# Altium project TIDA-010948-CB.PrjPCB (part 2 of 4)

## Sheet TIDA-010948-CB-Debug.SchDoc
size 431 x 279 mm; Date: Not shown in title block; ApprovedBy: Not shown in title block; CheckedBy: Not shown in title block; Author: Not shown in title block; CompanyName: Not shown in title block; Engineer: Not shown in title block; Organization: Not shown in title block; Address1: Not shown in title block; Address2: Not shown in title block; Address3: Not shown in title block; Address4: Not shown in title block; DocumentNumber: 4; Revision: Use project parameter SCH_Rev; SheetNumber: 4; SheetTotal: 11; PageSetup: Record=PageOptions¦CenterHorizontal=True¦CenterVertical=True¦PrintScale=1.00¦XCorrection=1.00¦YCorrection=1.00¦PrintKind=0¦BorderSize=5000000¦LeftOffset=0¦BottomOffset=0¦Orientation=2¦PaperLength=1000¦PaperWidth=1000¦Scale=100¦PaperSource=15¦PrintQuality=600¦MediaType=1¦DitherType=10¦PaperKind=Letter¦PrintScaleMode=1
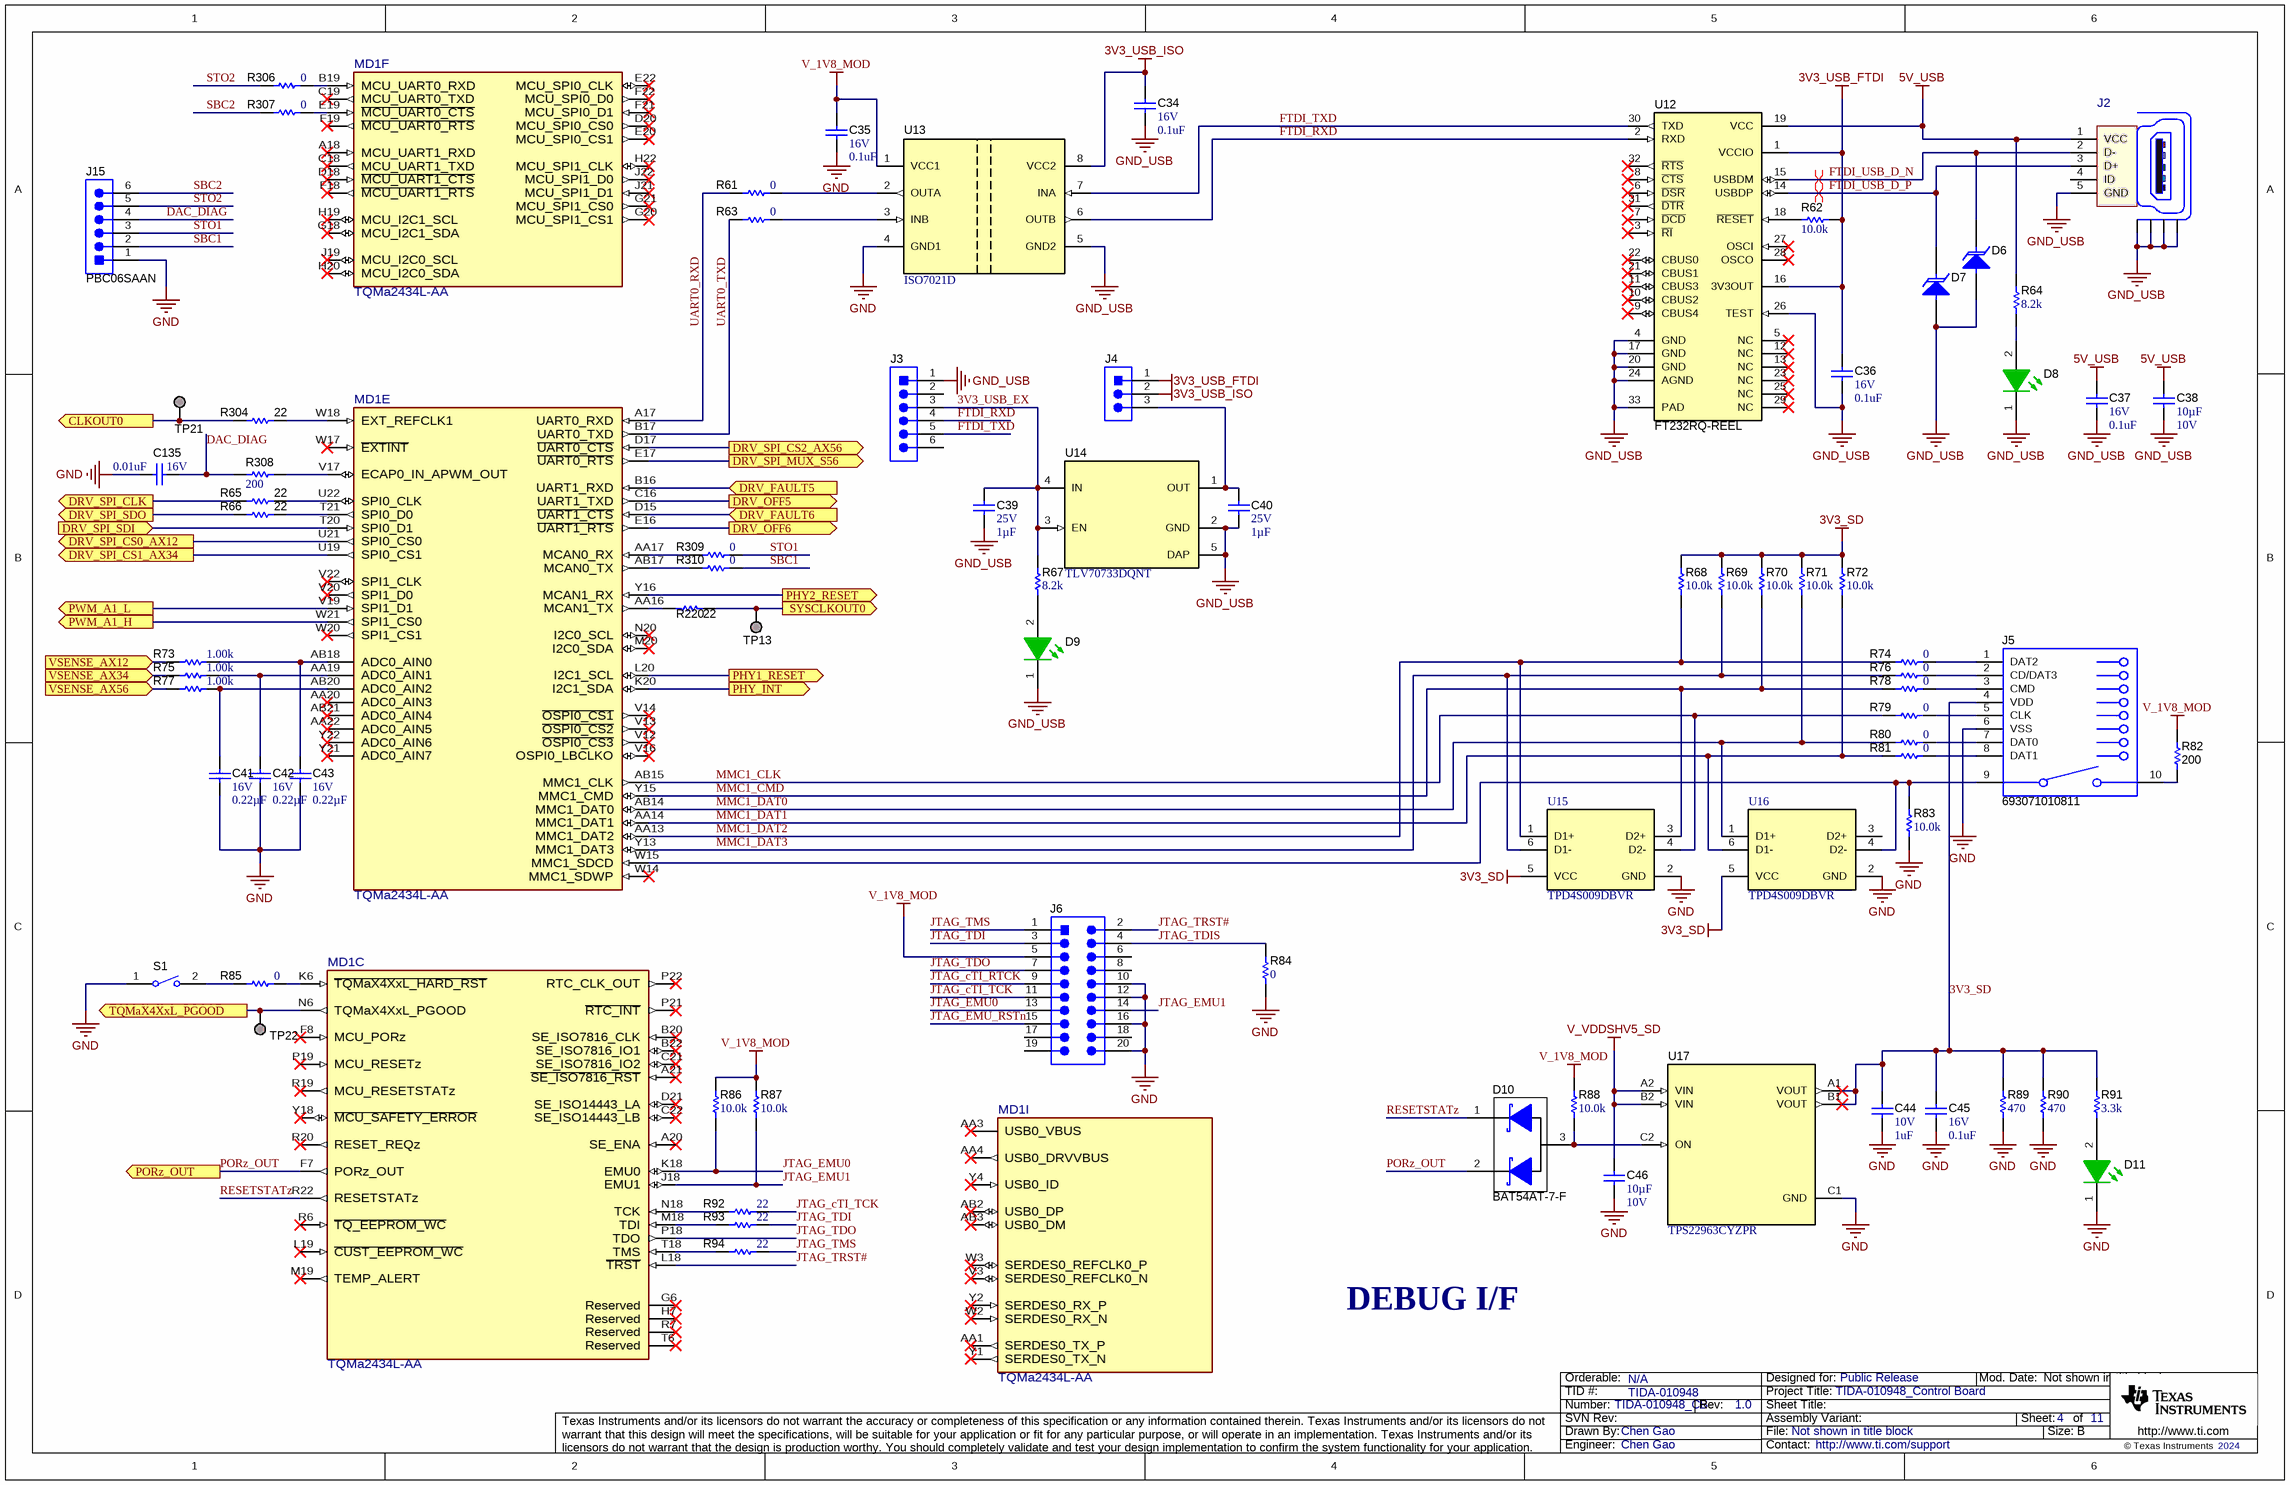
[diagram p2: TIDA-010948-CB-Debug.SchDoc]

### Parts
C34  VDC_V: 16V  ValueDisplayed: 0.1uF  [0402L]  (hidden comment: 885012105016)
C35  VDC_V: 16V  ValueDisplayed: 0.1uF  [0402L]  (hidden comment: 885012105016)
C36  VDC_V: 16V  ValueDisplayed: 0.1uF  [0402L]  (hidden comment: 885012105016)
C37  VDC_V: 16V  ValueDisplayed: 0.1uF  [0402L]  (hidden comment: 885012105016)
C38  Cap_F: 10µF  VDC_V: 10V  [0805L]  (hidden comment: 885012207026)
C39  VDC_V: 25V  ValueDisplayed: 1µF  [0402L]  (hidden comment: GRM155R61E105MA12D)
C40  VDC_V: 25V  ValueDisplayed: 1µF  [0402L]  (hidden comment: GRM155R61E105MA12D)
C41  VDC_V: 16V  ValueDisplayed: 0.22µF  [0402]  (hidden comment: GCM155R71C224KE02D)
C42  VDC_V: 16V  ValueDisplayed: 0.22µF  [0402]  (hidden comment: GCM155R71C224KE02D)
C43  VDC_V: 16V  ValueDisplayed: 0.22µF  [0402]  (hidden comment: GCM155R71C224KE02D)
C44  VDC_V: 10V  ValueDisplayed: 1uF  [0402L]  (hidden comment: 885012105012)
C45  VDC_V: 16V  ValueDisplayed: 0.1uF  [0402L]  (hidden comment: 885012105016)
C46  Cap_F: 10µF  VDC_V: 10V  [0805_HV]  (hidden comment: 885012207026)
C135  VDC_V: 16V  ValueDisplayed: 0.01uF  [0402]  (hidden comment: C1005X7R1C103K050BA)
D6  ESD321DPYR  [DPY0002A]  (value not drawn)
D7  ESD321DPYR  [DPY0002A]  (value not drawn)
D8  150040GS73240  [WL-SMCC_0402_Green]  (value not drawn)
D9  150040GS73240  [WL-SMCC_0402_Green]  (value not drawn)
D10  BAT54AT-7-F  [SOT-523]
D11  150040GS73240  [WL-SMCC_0402_Green]  (value not drawn)
J2  629105150521  [FP-629105150521_CONN_USB_8MM0_6MM6-MFG]  (value not drawn)
J3  61300611121  [WURTH_61300611121]  (value not drawn)
J4  61300311121  [WURTH_61300311121]  (value not drawn)
J5  693071010811  [Molex_693071010811]
J6  FTR-110-51-S-D-06  [Samtec_FTR-110-51-x-D-06]  (value not drawn)
J15  PBC06SAAN  [Sullins_PxC06SAAN]
MD1  TQMa2434L-AA  [FP-TQMa2434L-AA_LGA366-MFG]  (parts C,E,F,I of 9)
R61  ValueDisplayed: 0  [0402L]  (hidden comment: ERJ-2GE0R00X)
R62  ValueDisplayed: 10.0k  [0402L]  (hidden comment: CRCW040210K0FKED)
R63  ValueDisplayed: 0  [0402L]  (hidden comment: ERJ-2GE0R00X)
R64  ValueDisplayed: 8.2k  [0402L]  (hidden comment: CRCW04028K20JNED)
R65  ValueDisplayed: 22  [0402]  (hidden comment: CRCW040222R0JNED)
R66  ValueDisplayed: 22  [0402]  (hidden comment: CRCW040222R0JNED)
R67  ValueDisplayed: 8.2k  [0402L]  (hidden comment: CRCW04028K20JNED)
R68  ValueDisplayed: 10.0k  [0402L]  (hidden comment: CRCW040210K0FKED)
R69  ValueDisplayed: 10.0k  [0402L]  (hidden comment: CRCW040210K0FKED)
R70  ValueDisplayed: 10.0k  [0402L]  (hidden comment: CRCW040210K0FKED)
R71  ValueDisplayed: 10.0k  [0402L]  (hidden comment: CRCW040210K0FKED)
R72  ValueDisplayed: 10.0k  [0402L]  (hidden comment: CRCW040210K0FKED)
R73  ValueDisplayed: 1.00k  [0402L]  (hidden comment: CRCW04021K00FKED)
R74  ValueDisplayed: 0  [0402L]  (hidden comment: ERJ-2GE0R00X)
R75  ValueDisplayed: 1.00k  [0402L]  (hidden comment: CRCW04021K00FKED)
R76  ValueDisplayed: 0  [0402L]  (hidden comment: ERJ-2GE0R00X)
R77  ValueDisplayed: 1.00k  [0402L]  (hidden comment: CRCW04021K00FKED)
R78  ValueDisplayed: 0  [0402L]  (hidden comment: ERJ-2GE0R00X)
R79  ValueDisplayed: 0  [0402L]  (hidden comment: ERJ-2GE0R00X)
R80  ValueDisplayed: 0  [0402L]  (hidden comment: ERJ-2GE0R00X)
R81  ValueDisplayed: 0  [0402L]  (hidden comment: ERJ-2GE0R00X)
R82  ValueDisplayed: 200  [0402L]  (hidden comment: CRCW0402200RFKED)
R83  ValueDisplayed: 10.0k  [0402L]  (hidden comment: CRCW040210K0FKED)
R84  ValueDisplayed: 0  [0402L]  (hidden comment: ERJ-2GE0R00X)
R85  ValueDisplayed: 0  [0402L]  (hidden comment: ERJ-2GE0R00X)
R86  ValueDisplayed: 10.0k  [0402L]  (hidden comment: CRCW040210K0FKED)
R87  ValueDisplayed: 10.0k  [0402L]  (hidden comment: CRCW040210K0FKED)
R88  ValueDisplayed: 10.0k  [0402L]  (hidden comment: CRCW040210K0FKED)
R89  ValueDisplayed: 470  [0402L]  (hidden comment: CRCW0402470RJNED)
R90  ValueDisplayed: 470  [0402L]  (hidden comment: CRCW0402470RJNED)
R91  ValueDisplayed: 3.3k  [0402L]  (hidden comment: CRCW04023K30JNED)
R92  ValueDisplayed: 22  [0402L]  (hidden comment: CRCW040222R0JNED)
R93  ValueDisplayed: 22  [0402L]  (hidden comment: CRCW040222R0JNED)
R94  ValueDisplayed: 22  [0402L]  (hidden comment: CRCW040222R0JNED)
R220  ValueDisplayed: 22  [0402]  (hidden comment: CRCW040222R0JNED)
R304  ValueDisplayed: 22  [0402]  (hidden comment: CRCW040222R0JNED)
R306  ValueDisplayed: 0  [0402L]  (hidden comment: ERJ-2GE0R00X)
R307  ValueDisplayed: 0  [0402L]  (hidden comment: ERJ-2GE0R00X)
R308  ValueDisplayed: 200  [0402]  (hidden comment: CRCW0402200RFKED)
R309  ValueDisplayed: 0  [0402L]  (hidden comment: ERJ-2GE0R00X)
R310  ValueDisplayed: 0  [0402L]  (hidden comment: ERJ-2GE0R00X)
S1  434121025816  [SW_434121025816]  (value not drawn)
TP13  TESTPOINT  [TP_25MIL-SMT]  (value not drawn)  (no BOM)
TP21  TESTPOINT  [TP_25MIL-SMT]  (value not drawn)  (no BOM)
TP22  TESTPOINT  [TP_25MIL-SMT]  (value not drawn)  (no BOM)
U12  FT232RQ-REEL  [QFN32-5x5MM]
U13  PartNumber: ISO7021D  [D0008B_HV]  (hidden comment: ISO7721D)
U14  TLV70733DQNT  [DQN0004A]
U15  TPD4S009DBVR  [DBV0006A_L]
U16  TPD4S009DBVR  [DBV0006A_L]
U17  TPS22963CYZPR  [YZP0006AFAF]

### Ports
CLKOUT0 (out), DRV_FAULT5 (in), DRV_FAULT6 (in), DRV_OFF5 (out), DRV_OFF6 (out), DRV_SPI_CLK (out), DRV_SPI_CS0_AX12 (out), DRV_SPI_CS1_AX34 (out), DRV_SPI_CS2_AX56 (out), DRV_SPI_MUX_S56 (out), DRV_SPI_SDI (in), DRV_SPI_SDO (out), PHY1_RESET (out), PHY2_RESET (out), PHY_INT (out), PORz_OUT (out), PWM_A1_H (out), PWM_A1_L (out), SYSCLKOUT0 (out), TQMaX4XxL_PGOOD (out), VSENSE_AX12 (in), VSENSE_AX34 (in), VSENSE_AX56 (in)

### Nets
3V3_SD: C44.1 C45.1 J5.4(VDD) R68.2 R69.2 R70.2 R71.2 R72.2 R89.2 R90.2 R91.2 U15.5(VCC) U16.5(VCC) U17.A1(VOUT) U17.B1(VOUT)
3V3_USB_FTDI: C36.1 J4.1 R62.1 U12.1(VCCIO) U12.16(3V3OUT)
3V3_USB_ISO: C34.1 J4.2 U13.8(VCC2)
5V_USB: C37.1 C38.1 J2.1(VCC) R64.2 U12.19(VCC)
GND: C35.2 C41.1 C42.1 C43.1 C44.2 C45.2 C46.2 C135.2 D11.1(K) J5.6(VSS) J6.10 J6.12 J6.16 J6.20 J15.1 R83.1 R84.1 R89.1 R90.1 S1.1 U13.4(GND1) U15.2(GND) U16.2(GND) U17.C1(GND)
GND_USB: C34.2 C36.2 C37.2 C38.2 C39.2 C40.2 D6.2(A) D7.2(A) D8.1(K) D9.1(K) J2.5(GND) J2.Z1(Shield) J2.Z2(Shield) J2.Z3(Shield) J2.Z4(Shield) J3.1 U12.4(GND) U12.17(GND) U12.20(GND) U12.24(AGND) U12.26(TEST) U12.33(PAD) U13.5(GND2) U14.2(GND) U14.5(DAP)
V_1V8_MOD: C35.1 J6.5 R82.2 R86.2 R87.2 R88.2 U13.1(VCC1)
V_VDDSHV5_SD: C46.1 U17.A2(VIN) U17.B2(VIN)
3V3_USB_EX: C39.1 J3.3 R67.2 U14.3(EN) U14.4(IN)
CLKOUT0: R304.1 TP21.1 ; port CLKOUT0
DAC_DIAG: C135.1 J15.4 R308.1
DRV_FAULT5: MD1.B16(UART1_RXD) ; port DRV_FAULT5
DRV_FAULT6: MD1.D15(~{UART1_CTS}) ; port DRV_FAULT6
DRV_OFF5: MD1.C16(UART1_TXD) ; port DRV_OFF5
DRV_OFF6: MD1.E16(~{UART1_RTS}) ; port DRV_OFF6
DRV_SPI_CLK: R65.1 ; port DRV_SPI_CLK
DRV_SPI_CS0_AX12: MD1.U21(SPI0_CS0) ; port DRV_SPI_CS0_AX12
DRV_SPI_CS1_AX34: MD1.U19(SPI0_CS1) ; port DRV_SPI_CS1_AX34
DRV_SPI_CS2_AX56: MD1.D17(~{UART0_CTS}) ; port DRV_SPI_CS2_AX56
DRV_SPI_MUX_S56: MD1.E17(~{UART0_RTS}) ; port DRV_SPI_MUX_S56
DRV_SPI_SDI: MD1.T20(SPI0_D1) ; port DRV_SPI_SDI
DRV_SPI_SDO: R66.1 ; port DRV_SPI_SDO
FTDI_RXD: J3.4 U12.2(RXD) U13.6(OUTB)
FTDI_TXD: J3.5 U12.30(TXD) U13.7(INA)
FTDI_USB_D_N: D6.1(K) J2.2(D-) U12.15(USBDM)
FTDI_USB_D_P: D7.1(K) J2.3(D+) U12.14(USBDP)
JTAG_cTI_RTCK: J6.9
JTAG_cTI_TCK: J6.11 R92.2
JTAG_EMU0: J6.13 MD1.K18(EMU0) R86.1
JTAG_EMU1: J6.14 MD1.J18(EMU1) R87.1
JTAG_EMU_RSTn: J6.15
JTAG_TDI: J6.3 R93.2
JTAG_TDIS: J6.4 R84.2
JTAG_TDO: J6.7 MD1.P18(TDO)
JTAG_TMS: J6.1 R94.2
JTAG_TRST#: J6.2 MD1.L18(~{TRST})
MMC1_CLK: MD1.AB15(MMC1_CLK) R79.1 U15.4(D2-)
MMC1_CMD: MD1.Y15(MMC1_CMD) R70.1 R78.1 U15.3(D2+)
MMC1_DAT0: MD1.AB14(MMC1_DAT0) R71.1 R80.1 U16.1(D1+)
MMC1_DAT1: MD1.AA14(MMC1_DAT1) R72.1 R81.1 U16.6(D1-)
MMC1_DAT2: MD1.AA13(MMC1_DAT2) R68.1 R74.1 U15.1(D1+)
MMC1_DAT3: MD1.Y13(MMC1_DAT3) R69.1 R76.1 U15.6(D1-)
PHY1_RESET: MD1.L20(I2C1_SCL) ; port PHY1_RESET
PHY2_RESET: MD1.Y16(MCAN1_RX) ; port PHY2_RESET
PHY_INT: MD1.K20(I2C1_SDA) ; port PHY_INT
PORz_OUT: D10.2(K) MD1.F7(PORz_OUT) ; port PORz_OUT
PWM_A1_H: MD1.W21(SPI1_CS0) ; port PWM_A1_H
PWM_A1_L: MD1.V19(SPI1_D1) ; port PWM_A1_L
RESETSTATz: D10.1(A) MD1.R22(RESETSTATz)
SBC1: J15.2 R310.2
SBC2: J15.6 R307.1
STO1: J15.3 R309.2
STO2: J15.5 R306.1
SYSCLKOUT0: R220.1 TP13.1 ; port SYSCLKOUT0
TQMaX4XxL_PGOOD: MD1.N6(TQMaX4XxL_PGOOD) TP22.1 ; port TQMaX4XxL_PGOOD
UART0_RXD: MD1.A17(UART0_RXD) R61.1
UART0_TXD: MD1.B17(UART0_TXD) R63.1
VSENSE_AX12: R73.1 ; port VSENSE_AX12
VSENSE_AX34: R75.1 ; port VSENSE_AX34
VSENSE_AX56: R77.1 ; port VSENSE_AX56
NetC40_1: C40.1 J4.3 U14.1(OUT)
NetC41_2: C41.2 MD1.AB20(ADC0_AIN2) R77.2
NetC42_2: C42.2 MD1.AA19(ADC0_AIN1) R75.2
NetC43_2: C43.2 MD1.AB18(ADC0_AIN0) R73.2
NetD8_2: D8.2(A) R64.1
NetD9_2: D9.2(A) R67.1
NetD10_3: D10.3(A) R88.1 U17.C2(ON)
NetD11_2: D11.2(A) R91.1
NetJ5_1: J5.1(DAT2) R74.2
NetJ5_2: J5.2(CD/DAT3) R76.2
NetJ5_3: J5.3(CMD) R78.2
NetJ5_5: J5.5(CLK) R79.2
NetJ5_7: J5.7(DAT0) R80.2
NetJ5_8: J5.8(DAT1) R81.2
NetJ5_9: J5.9 MD1.W15(MMC1_SDCD) R83.2 U16.4(D2-)
NetJ5_10: J5.10 R82.1
NetMD1_AA16: MD1.AA16(MCAN1_TX) R220.2
NetMD1_AA17: MD1.AA17(MCAN0_RX) R309.1
NetMD1_AB17: MD1.AB17(MCAN0_TX) R310.1
NetMD1_B19: MD1.B19(MCU_UART0_RXD) R306.2
NetMD1_E19: MD1.E19(~{MCU_UART0_CTS}) R307.2
NetMD1_K6: MD1.K6(~{TQMaX4XxL_HARD_RST}) R85.2
NetMD1_M18: MD1.M18(TDI) R93.1
NetMD1_N18: MD1.N18(TCK) R92.1
NetMD1_T18: MD1.T18(TMS) R94.1
NetMD1_T21: MD1.T21(SPI0_D0) R66.2
NetMD1_U22: MD1.U22(SPI0_CLK) R65.2
NetMD1_V17: MD1.V17(ECAP0_IN_APWM_OUT) R308.2
NetMD1_W18: MD1.W18(EXT_REFCLK1) R304.2
NetR61_2: R61.2 U13.2(OUTA)
NetR62_2: R62.2 U12.18(~{RESET})
NetR63_2: R63.2 U13.3(INB)
NetR85_1: R85.1 S1.2

Not connected (* = marked no-connect by the designer): J2 4(ID); J3 2 6; J6 6 8 17 18 19; MD1 A18(MCU_UART1_RXD)* A20(SE_ENA)* A21(~{SE_ISO7816_RST})* AA1(SERDES0_TX_P)* AA3(USB0_VBUS)* AA4(USB0_DRVVBUS)* AA20(ADC0_AIN3)* AA22(ADC0_AIN5)* AB2(USB0_DP)* AB3(USB0_DM)* AB21(ADC0_AIN4)* B20(SE_ISO7816_CLK)* B22(SE_ISO7816_IO1)* C18(MCU_UART1_TXD)* C19(MCU_UART0_TXD)* C21(SE_ISO7816_IO2)* C22(SE_ISO14443_LB)* D18(~{MCU_UART1_CTS})* D20(MCU_SPI0_CS0)* D21(SE_ISO14443_LA)* E20(MCU_SPI0_CS1)* E22(MCU_SPI0_CLK)* F8(MCU_PORz)* F18(~{MCU_UART1_RTS})* F19(~{MCU_UART0_RTS})* F21(MCU_SPI0_D1)* F22(MCU_SPI0_D0)* G6(Reserved)* G18(MCU_I2C1_SDA)* G20(MCU_SPI1_CS1)* G21(MCU_SPI1_CS0)* H7(Reserved)* H19(MCU_I2C1_SCL)* H20(MCU_I2C0_SDA)* H22(MCU_SPI1_CLK)* J19(MCU_I2C0_SCL)* J21(MCU_SPI1_D1)* J22(MCU_SPI1_D0)* L19(~{CUST_EEPROM_WC})* M19(TEMP_ALERT)* M20(I2C0_SDA)* N20(I2C0_SCL)* P19(MCU_RESETz)* P21(~{RTC_INT})* P22(RTC_CLK_OUT)* R6(~{TQ_EEPROM_WC})* R7(Reserved)* R19(MCU_RESETSTATz)* R20(RESET_REQz)* T6(Reserved)* V3(SERDES0_REFCLK0_N)* V12(~{OSPI0_CS3})* V13(~{OSPI0_CS2})* V14(~{OSPI0_CS1})* V16(OSPI0_LBCLKO)* V20(SPI1_D0)* V22(SPI1_CLK)* W2(SERDES0_RX_N)* W3(SERDES0_REFCLK0_P)* W14(MMC1_SDWP)* W17(~{EXTINT})* W20(SPI1_CS1)* Y1(SERDES0_TX_N)* Y2(SERDES0_RX_P)* Y4(USB0_ID)* Y18(~{MCU_SAFETY_ERROR})* Y21(ADC0_AIN7)* Y22(ADC0_AIN6)*; U12 3(~{RI})* 5(NC)* 6(~{DSR})* 7(~{DCD})* 8(~{CTS})* 9(CBUS4)* 10(CBUS2)* 11(CBUS3)* 12(NC)* 13(NC)* 21(CBUS1)* 22(CBUS0)* 23(NC)* 25(NC)* 27(OSCI)* 28(OSCO)* 29(NC)* 31(~{DTR})* 32(~{RTS})*; U16 3(D2+)

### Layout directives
differential pair; differential pair class USB: FTDI_USB_D_N, FTDI_USB_D_P

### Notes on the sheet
- DEBUG I/F

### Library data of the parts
C34-C37 C45 = CMP-0006223-2: CAP, CERM, 0.1 uF, 16 V, +/- 20%, X5R, 0402; Manufacturer: Wurth Elektronik; TaMin_C: -55°C; Polarized: N; SizeAreaWB_mm2: 3; Value1: Unknown; U/M: EA; Value: 0.1uF; TaMax_C: 85°C; SizeZ_mm: 0.6; SizeX_mm: 1; SizeY_mm: 0.5; Cap_Case: 0402; Cap_F: 100nF; AEC Category: Q200
C38 C46 = CMP-0007691-2: CAP, CERM, 10 uF, 10 V, +/- 10%, X7R, 0805; Manufacturer: Wurth Elektronik; TaMin_C: -55°C; Polarized: N; SizeAreaWB_mm2: 6.75; Value1: Unknown; U/M: EA; Value: 10uF; TaMax_C: 125°C; SizeZ_mm: 1.45; SizeX_mm: 2; SizeY_mm: 1.25; Cap_Case: 0805; SizeArea_mm2: 2.5; AEC Category: Q200
C39 C40 = CMP-0078625-1: CAP, CERM, 1 µF, 25 V,+/- 20%, X5R, 0402; Manufacturer: MuRata; SizeAreaWB_mm2: 3; SizeArea_mm2: 0.5; AEC Qualified: N; AEC Category: Q200; Value: 1uF; TaMax_C: 85°C; SizeZ_mm: 0.6; TaMin_C: -55°C; U/M: EA; SizeX_mm: 1; Cap_Case: 0402
C41-C43 = CMP-0078265-1: CAP, CERM, 0.22 µF, 16 V,+/- 10%, X7R, AEC-Q200 Grade 1, 0402; Manufacturer: MuRata; TaMin_C: -55°C; Polarized: N; SizeAreaWB_mm2: 3; U/M: EA; Value: 0.22uF; TaMax_C: 125°C; SizeZ_mm: 0.6; SizeX_mm: 1; SizeY_mm: 0.5; AEC Qualified: Y; Cap_F: 220nF; AEC Category: Q200
C44 = CMP-0064924-2: CAP, CERM, 1 uF, 10 V,+/- 20%, X5R, 0402; Manufacturer: Wurth Elektronik; TaMin_C: -55°C; Polarized: N; SizeAreaWB_mm2: 3; Value1: Unknown; U/M: EA; Value: 1uF; TaMax_C: 85°C; SizeZ_mm: 0.6; SizeX_mm: 1; SizeY_mm: 0.5; Cap_Case: 0402; Cap_F: 1µF; AEC Category: Q200
C135 = CMP-0006292-2: CAP, CERM, 0.01 uF, 16 V, +/- 10%, X7R, 0402; Manufacturer: TDK; TaMin_C: -55°C; ESR_ohm: 62.3m; Polarized: N; SizeAreaWB_mm2: 3; Value1: 0.0623 ohm; U/M: EA; Value: 0.01uF; TaMax_C: 125°C; SizeZ_mm: 0.6; SizeX_mm: 1; SizeY_mm: 0.5; Cap_F: 10nF; AEC Category: Q200
D6 D7 = CMP-0860710-3: 1-channel 30 kV ESD protection diode with low capacitance (< 1pF) in 0402 package, DPY0002A (X1SON-2); Manufacturer: Texas Instruments; CompType: IC; SizeY_mm: 0.6; SizeAreaWB_mm2: 3.2; SizeZ_mm: 0.45; AEC Category: Q200; AEC Qualified: N; Rating: Catalog; SizeX_mm: 1
D8 D9 D11 = CMP-0081765-2: LED, Green, SMD; Manufacturer: Wurth Elektronik; Vr_V: 5V; Io_A: 20mA; Tjmax_C: 95°C; Ir_A: 10µA; Power_TotalModule: 99mW; Value2: 3.2V; SizeArea_mm2: 0.5; SizeX_mm: 1; Value1: 0.099W; Angle: 120; Type: InGaN; SizeAreaWB_mm2: 3
D10 = CMP-0077018-2: Diode, Schottky, 30 V, 0.2 A, SOT-523; Manufacturer: Diodes Inc.; TJmax_C: 125°C; SizeX_mm: 1.6; SizeZ_mm: 0.8; Green_REACh: Incomplete; Value2: 1V; Io_A: 200mA; AEC Category: Q101; Green_Lifecycle: Not Set; Value: 30V; Value1: 0.2A; SizeAreaWB_mm2: 6.76; SizeArea_mm2: 2.56
J2 = CMP-0086695-3: USB - micro B USB 2.0 Receptacle Connector 5 Position Surface Mount, Right Angle; Through Hole; Manufacturer: Wurth Electronics; Shrouded: true; Voltage_V: 30V; Current_A: 3A; ContactFinish: Gold
J3 = CMP-0054801-2: Header, 2.54 mm, 6x1, Gold, TH; Manufacturer: Wurth Elektronik; Cert_UL: Y; Gender: Male; Row_Count: 1; Shrouded: N; Pitch_mm: 2.54
J4 = CMP-0054796-4: Header, 2.54 mm, 3x1, Gold, TH; Manufacturer: Wurth Elektronik; Green_REACh: Passed; CT: FALSE; CNHeader: TRUE; Green_Lifecycle: Active
J5 = CMP-0078832-1: MicroSD Card Connector, R/A, Gold, SMT; Manufacturer: Wurth Elektronik; Pitch_mm: 1.1; Gender: Female; Cert_UL: Y; Voltage_V: 100V; Current_A: 500mA; Row_Count: 1
J6 = CMP-0075640-2: Header, 1.27mm, 10x2, Tin, SMT; Manufacturer: Samtec; Pitch_mm: 1.27; Gender: Male; Cert_UL: Y; Green_REACh: Passed; Current_A: 3.1A; Shrouded: N; RowSpacing_mm: 2.54; Green_Lifecycle: Active; Row_Count: 2
J15 = CMP-0054603-1: Header, 2.54mm, 6x1, Gold, TH; Manufacturer: Sullins Connector Solutions; CNHeader: TRUE; Current_A: 3A; Green_Lifecycle: Not Set; Shrouded: N; Gender: Male; Green_REACh: Incomplete; Row_Count: 1; Pitch_mm: 2.54; CT: FALSE; Cert_UL: Y
MD1 = CMP-0120622-1: Embedded Cortex®- R5F module based on TI AM243x for headless Applications with Real - time demand; Manufacturer: TQ-Group; SizeZ_mm: 6.34mm; AEC Qualified: No; Core Architecture: ARM Cortex-R5F; Frequency_Fixed: 800MHz; Interface: I2C,SPI,UART,CAN,USB,Ethernet,PCIe; Max Supply Voltage: 5.25V; Memory Size: 64MBytes; Memory Type: FLASH,NOR; Min Supply Voltage: 4.75V; Number Of A/D Converters: 1; Number Of Cores: 2; Number Of Ethernet Channels: 6; Number Of Spi Channels: 8; Number Of Uart Channels: 9; Ram Size: 1GBytes
R61 R63 R74 R76 R78-R81 R84 R85 R306 R307 R309 R310 = CMP-0026992-3: RES, 0, 5%, 0.1 W, AEC-Q200 Grade 0, 0402; Manufacturer: Panasonic; Power_W: 100mW; TempCo: 600 ppm/C; Value_Code: 0000; Value: 0; EIA_Code: E24; SizeX_mm: 1; SizeY_mm: 0.5; SizeZ_mm: 0.6; Value2: 0.1W; AEC Qualified: Y; VDC_V: 50V; AEC Category: Q200; SizeAreaWB_mm2: 3
R62 R68-R72 R83 R86-R88 = CMP-0025958-3: RES, 10.0 k, 1%, 0.063 W, AEC-Q200 Grade 0, 0402; Manufacturer: Vishay-Dale; Power_W: 63mW; TempCo: 100 ppm/C; Value_Code: 10k0; Value: 10.0k; EIA_Code: E96; Res_ohm: 10k; SizeX_mm: 1; SizeY_mm: 0.5; SizeZ_mm: 0.6; Value2: 0.063W; AEC Qualified: Y; VDC_V: 50V; AEC Category: Q200; AEC Grade: 0
R64 R67 = CMP-0026982-5: RES, 8.2 k, 5%, 0.063 W, AEC-Q200 Grade 0, 0402; Manufacturer: Vishay-Dale; Power_W: 63mW; TempCo: 200 ppm/C; Value_Code: 8k20; Value: 8.2k; EIA_Code: E24; SizeX_mm: 1; SizeY_mm: 0.5; SizeZ_mm: 0.6; Value2: 0.063W; AEC Qualified: Y; VDC_V: 50V; AEC Category: Q200; AEC Grade: 0
R65 R66 R92-R94 R220 R304 = CMP-0026880-3: RES, 22, 5%, 0.063 W, AEC-Q200 Grade 0, 0402; Manufacturer: Vishay-Dale; Power_W: 63mW; TempCo: 200 ppm/C; Value_Code: 22R0; Value: 22; EIA_Code: E24; SizeX_mm: 1; SizeY_mm: 0.5; SizeZ_mm: 0.6; Value2: 0.063W; AEC Qualified: Y; VDC_V: 50V; AEC Category: Q200; AEC Grade: 0
R73 R75 R77 = CMP-0026071-3: RES, 1.00 k, 1%, 0.063 W, AEC-Q200 Grade 0, 0402; Manufacturer: Vishay-Dale; Power_W: 63mW; TempCo: 100 ppm/C; Value_Code: 1k00; Value: 1.00k; EIA_Code: E96; Res_ohm: 1k; SizeX_mm: 1; SizeY_mm: 0.5; SizeZ_mm: 0.6; Value2: 0.063W; AEC Qualified: Y; VDC_V: 50V; AEC Category: Q200; AEC Grade: 0
R82 R308 = CMP-0026159-2: RES, 200, 1%, 0.063 W, AEC-Q200 Grade 0, 0402; Manufacturer: Vishay-Dale; Power_W: 63mW; TempCo: 100 ppm/C; Value_Code: 200R; Value: 200; EIA_Code: E96; SizeX_mm: 1; SizeY_mm: 0.5; SizeZ_mm: 0.6; Value2: 0.063W; AEC Qualified: Y; VDC_V: 50V; AEC Category: Q200; AEC Grade: 0
R89 R90 = CMP-0026934-3: RES, 470, 5%, 0.063 W, AEC-Q200 Grade 0, 0402; Manufacturer: Vishay-Dale; Power_W: 63mW; TempCo: 200 ppm/C; Value_Code: 470R; Value: 470; EIA_Code: E24; SizeX_mm: 1; SizeY_mm: 0.5; SizeZ_mm: 0.6; Value2: 0.063W; AEC Qualified: Y; VDC_V: 50V; AEC Category: Q200; AEC Grade: 0
R91 = CMP-0026918-5: RES, 3.3 k, 5%, 0.063 W, AEC-Q200 Grade 0, 0402; Manufacturer: Vishay-Dale; Power_W: 63mW; TempCo: 200 ppm/C; Value_Code: 3k30; Value: 3.3k; EIA_Code: E24; SizeX_mm: 1; SizeY_mm: 0.5; SizeZ_mm: 0.6; Value2: 0.063W; AEC Qualified: Y; VDC_V: 50V; AEC Category: Q200; AEC Grade: 0
S1 = CMP-0002196-2: Switch, Tactile, SPST, 12 V, SMD; Manufacturer: Wurth Elektronik; CurrentRating_mA: 50A; PositionCount: 1; VDC_V: 12V; SwitchFunction: Off-On
TP13 TP21 TP22 = CMP-0078143-3: TEST POINT.  No entry in BOM.
U12 = CMP-0004929-1: Future Technology Devices International Ltd. FT232R USB UART IC, QFN32; Manufacturer: FTDI
U13 = CMP-0085670-1: High Speed, Robust EMC Reinforced Dual-Channel Digital Isolator, D0008B (SOIC-8); Manufacturer: Texas Instruments; Alternate PartNumber: ISO7021DR; SizeX_mm: 6; SizeAreaWB_mm2: 55.2; AEC Qualified: N; SizeArea_mm2: 29.4; CompType: IC; Rating: Catalog; SizeZ_mm: 1.75; SizeY_mm: 4.9; AEC Category: Q200
U14 = CMP-0035981-2: Single Output Low Noise LDO, 200 mA, Fixed 3.3 V Output, 2 to 5.5 V Input, 4-pin X2SON(DQN), -40 to 85 degC, Green (RoHS & no Sb/Br); Manufacturer: Texas Instruments; Alternate PartNumber: TLV70733DQNR; Accuracy(%): 1.5; Fixed Output Options(V): 3.3; Iout(Max)(A): 0.2; SubFamily: Single Channel LDO; Vin(Min)(V): 2; Vdo(Typ)(mV): 250; Iq(Typ)(mA): 0.02; Vin(Max)(V): 5.5; AEC Category: Q200; AEC Qualified: N; CompType: IC; SizeAreaWB_mm2: 4; SizeArea_mm2: 1; SizeZ_mm: 0.4
U15 U16 = CMP-0043117-1: ESD Solution for High-Speed Differential Interface, 4 Channels, -40 to +85 degC, 6-pin SOT-32 (DBV), Green (RoHS & no Sb/Br); Manufacturer: Texas Instruments; IO Leakage Current(nA): 10; Breakdown Voltage(Min)(V): 9; Differential Capacitance(pF): 0.05; IEC 61000-4-2 Contact(+/- kV): 8; IO Capacitance(Typ)(pF): 0.8
U17 = CMP-0066658-1: 5.5V, 3A, 13.8mΩ Load Switch with Reverse Current Protection, YZP0006AFAF (DSBGA-6); Alternate PartNumber: TPS22963CYZPT; Alternate Manufacturer: Texas Instruments; Green_Lifecycle: Active; SizeAreaWB_mm2: 4.742364; Green_REACh: Passed; U/M: EA; SizeZ_mm: 0.5; SizeX_mm: 0.942; SizeY_mm: 1.442; SizeArea_mm2: 1.358364; CompType: IC

## Sheet TIDA-010948-CB-SDFM.SchDoc
size 431 x 279 mm; Date: Not shown in title block; ApprovedBy: Not shown in title block; CheckedBy: Not shown in title block; Author: Not shown in title block; CompanyName: Not shown in title block; Engineer: Not shown in title block; Organization: Not shown in title block; Address1: Not shown in title block; Address2: Not shown in title block; Address3: Not shown in title block; Address4: Not shown in title block; DocumentNumber: 5; Revision: Use project parameter SCH_Rev; SheetNumber: 5; SheetTotal: 11; PageSetup: Record=PageOptions¦CenterHorizontal=True¦CenterVertical=True¦PrintScale=1.00¦XCorrection=1.00¦YCorrection=1.00¦PrintKind=0¦BorderSize=5000000¦LeftOffset=0¦BottomOffset=0¦Orientation=2¦PaperLength=1000¦PaperWidth=1000¦Scale=100¦PaperSource=15¦PrintQuality=600¦MediaType=1¦DitherType=10¦PaperKind=Letter¦PrintScaleMode=1
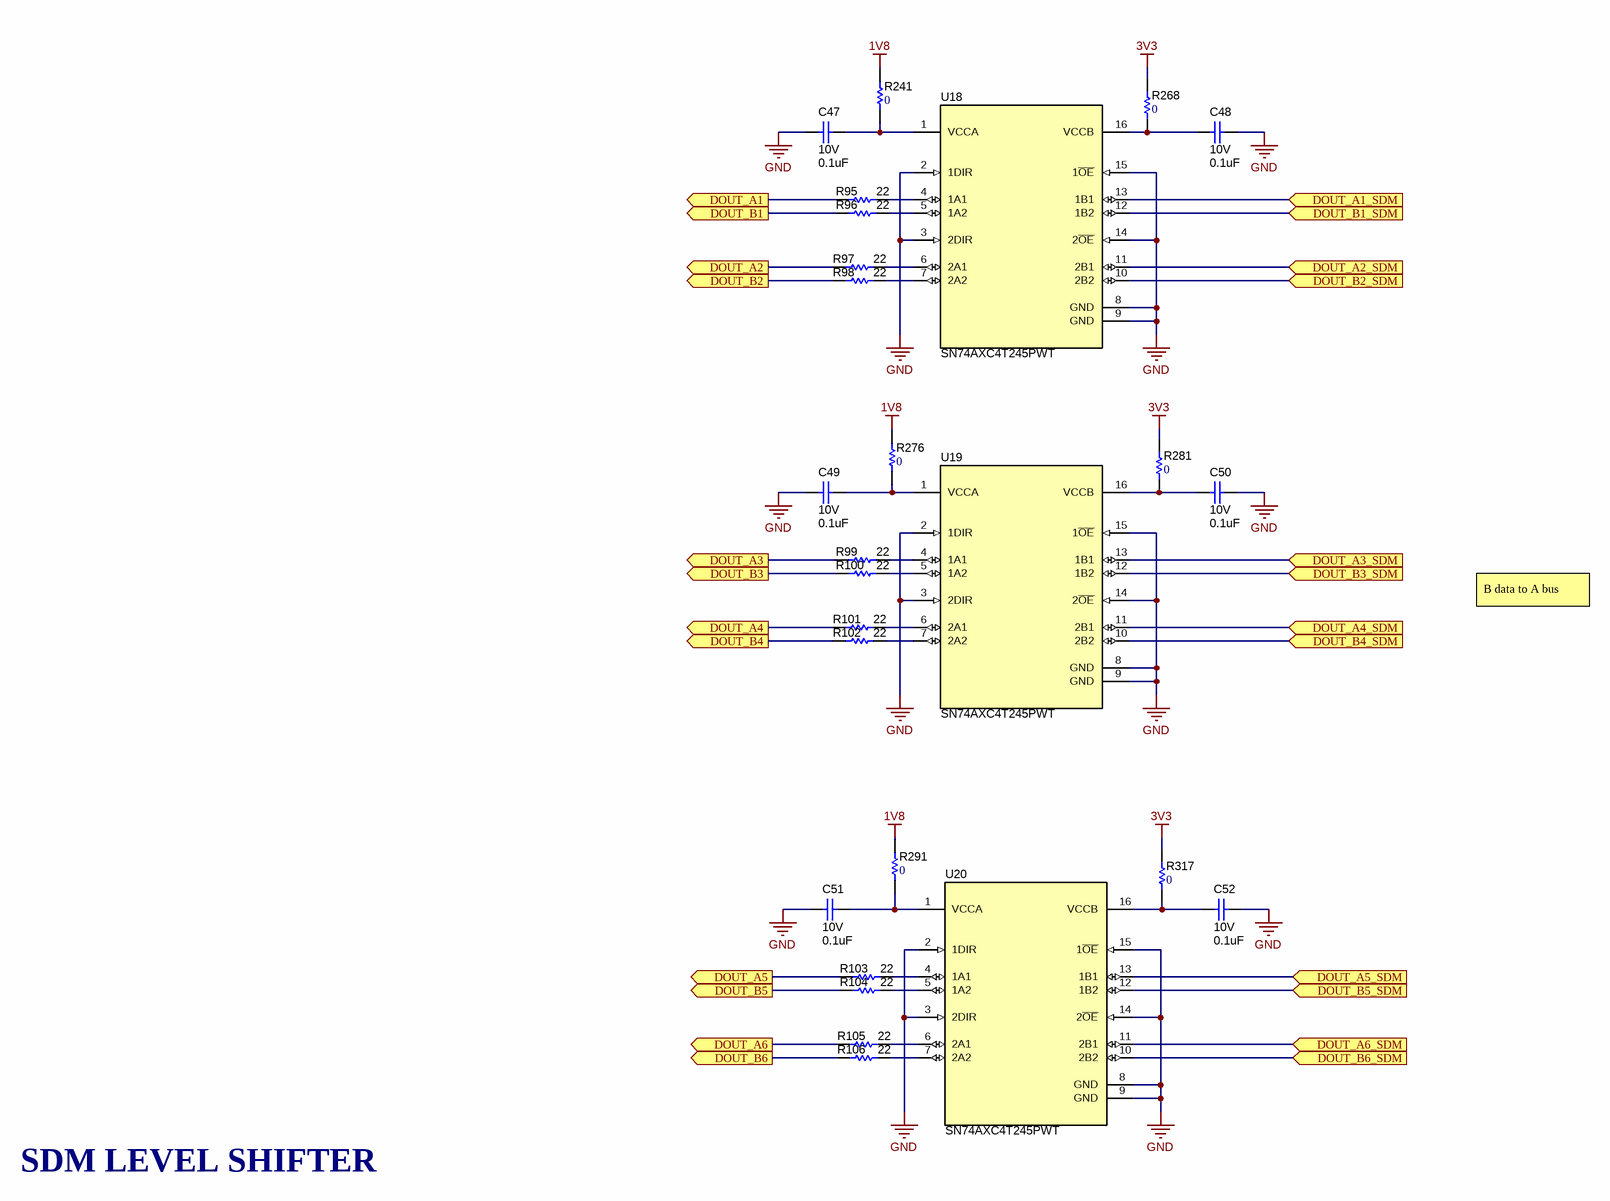
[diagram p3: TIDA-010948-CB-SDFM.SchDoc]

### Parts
C47  VDC_V: 10V  ValueDisplayed: 0.1uF  [0402]  (hidden comment: GRM155R71A104KA01D)
C48  VDC_V: 10V  ValueDisplayed: 0.1uF  [0402]  (hidden comment: GRM155R71A104KA01D)
C49  VDC_V: 10V  ValueDisplayed: 0.1uF  [0402]  (hidden comment: GRM155R71A104KA01D)
C50  VDC_V: 10V  ValueDisplayed: 0.1uF  [0402]  (hidden comment: GRM155R71A104KA01D)
C51  VDC_V: 10V  ValueDisplayed: 0.1uF  [0402]  (hidden comment: GRM155R71A104KA01D)
C52  VDC_V: 10V  ValueDisplayed: 0.1uF  [0402]  (hidden comment: GRM155R71A104KA01D)
R95  ValueDisplayed: 22  [0402]  (hidden comment: CRCW040222R0JNED)
R96  ValueDisplayed: 22  [0402]  (hidden comment: CRCW040222R0JNED)
R97  ValueDisplayed: 22  [0402]  (hidden comment: CRCW040222R0JNED)
R98  ValueDisplayed: 22  [0402]  (hidden comment: CRCW040222R0JNED)
R99  ValueDisplayed: 22  [0402]  (hidden comment: CRCW040222R0JNED)
R100  ValueDisplayed: 22  [0402]  (hidden comment: CRCW040222R0JNED)
R101  ValueDisplayed: 22  [0402]  (hidden comment: CRCW040222R0JNED)
R102  ValueDisplayed: 22  [0402]  (hidden comment: CRCW040222R0JNED)
R103  ValueDisplayed: 22  [0402]  (hidden comment: CRCW040222R0JNED)
R104  ValueDisplayed: 22  [0402]  (hidden comment: CRCW040222R0JNED)
R105  ValueDisplayed: 22  [0402]  (hidden comment: CRCW040222R0JNED)
R106  ValueDisplayed: 22  [0402]  (hidden comment: CRCW040222R0JNED)
R241  ValueDisplayed: 0  [0402L]  (hidden comment: ERJ-2GE0R00X)
R268  ValueDisplayed: 0  [0402L]  (hidden comment: ERJ-2GE0R00X)
R276  ValueDisplayed: 0  [0402L]  (hidden comment: ERJ-2GE0R00X)
R281  ValueDisplayed: 0  [0402L]  (hidden comment: ERJ-2GE0R00X)
R291  ValueDisplayed: 0  [0402L]  (hidden comment: ERJ-2GE0R00X)
R317  ValueDisplayed: 0  [0402L]  (hidden comment: ERJ-2GE0R00X)
U18  SN74AXC4T245PWT  [PW0016A_N]
U19  SN74AXC4T245PWT  [PW0016A_N]
U20  SN74AXC4T245PWT  [PW0016A_N]

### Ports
DOUT_A1 (out), DOUT_A1_SDM (in), DOUT_A2 (out), DOUT_A2_SDM (in), DOUT_A3 (out), DOUT_A3_SDM (in), DOUT_A4 (out), DOUT_A4_SDM (in), DOUT_A5 (out), DOUT_A5_SDM (in), DOUT_A6 (out), DOUT_A6_SDM (in), DOUT_B1 (out), DOUT_B1_SDM (in), DOUT_B2 (out), DOUT_B2_SDM (in), DOUT_B3 (out), DOUT_B3_SDM (in), DOUT_B4 (out), DOUT_B4_SDM (in), DOUT_B5 (out), DOUT_B5_SDM (in), DOUT_B6 (out), DOUT_B6_SDM (in)

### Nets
1V8: R241.2 R276.2 R291.2
3V3: R268.2 R281.2 R317.2
GND: C47.1 C48.2 C49.1 C50.2 C51.1 C52.2 U18.2(1DIR) U18.3(2DIR) U18.8(GND) U18.9(GND) U18.14(2~{OE}) U18.15(1~{OE}) U19.2(1DIR) U19.3(2DIR) U19.8(GND) U19.9(GND) U19.14(2~{OE}) U19.15(1~{OE}) U20.2(1DIR) U20.3(2DIR) U20.8(GND) U20.9(GND) U20.14(2~{OE}) U20.15(1~{OE})
DOUT_A1: R95.1 ; port DOUT_A1
DOUT_A1_SDM: U18.13(1B1) ; port DOUT_A1_SDM
DOUT_A2: R97.1 ; port DOUT_A2
DOUT_A2_SDM: U18.11(2B1) ; port DOUT_A2_SDM
DOUT_A3: R99.1 ; port DOUT_A3
DOUT_A3_SDM: U19.13(1B1) ; port DOUT_A3_SDM
DOUT_A4: R101.1 ; port DOUT_A4
DOUT_A4_SDM: U19.11(2B1) ; port DOUT_A4_SDM
DOUT_A5: R103.1 ; port DOUT_A5
DOUT_A5_SDM: U20.13(1B1) ; port DOUT_A5_SDM
DOUT_A6: R105.1 ; port DOUT_A6
DOUT_A6_SDM: U20.11(2B1) ; port DOUT_A6_SDM
DOUT_B1: R96.1 ; port DOUT_B1
DOUT_B1_SDM: U18.12(1B2) ; port DOUT_B1_SDM
DOUT_B2: R98.1 ; port DOUT_B2
DOUT_B2_SDM: U18.10(2B2) ; port DOUT_B2_SDM
DOUT_B3: R100.1 ; port DOUT_B3
DOUT_B3_SDM: U19.12(1B2) ; port DOUT_B3_SDM
DOUT_B4: R102.1 ; port DOUT_B4
DOUT_B4_SDM: U19.10(2B2) ; port DOUT_B4_SDM
DOUT_B5: R104.1 ; port DOUT_B5
DOUT_B5_SDM: U20.12(1B2) ; port DOUT_B5_SDM
DOUT_B6: R106.1 ; port DOUT_B6
DOUT_B6_SDM: U20.10(2B2) ; port DOUT_B6_SDM
NetC47_2: C47.2 R241.1 U18.1(VCCA)
NetC48_1: C48.1 R268.1 U18.16(VCCB)
NetC49_2: C49.2 R276.1 U19.1(VCCA)
NetC50_1: C50.1 R281.1 U19.16(VCCB)
NetC51_2: C51.2 R291.1 U20.1(VCCA)
NetC52_1: C52.1 R317.1 U20.16(VCCB)
NetR95_2: R95.2 U18.4(1A1)
NetR96_2: R96.2 U18.5(1A2)
NetR97_2: R97.2 U18.6(2A1)
NetR98_2: R98.2 U18.7(2A2)
NetR99_2: R99.2 U19.4(1A1)
NetR100_2: R100.2 U19.5(1A2)
NetR101_2: R101.2 U19.6(2A1)
NetR102_2: R102.2 U19.7(2A2)
NetR103_2: R103.2 U20.4(1A1)
NetR104_2: R104.2 U20.5(1A2)
NetR105_2: R105.2 U20.6(2A1)
NetR106_2: R106.2 U20.7(2A2)

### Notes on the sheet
- B data to A bus
- SDM LEVEL SHIFTER

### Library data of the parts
C47-C52 = CMP-0006629-2: CAP, CERM, 0.1 uF, 10 V, +/- 10%, X7R, 0402; Manufacturer: MuRata; TaMin_C: -55°C; Polarized: N; SizeAreaWB_mm2: 3; Value1: Unknown; U/M: EA; Value: 0.1uF; TaMax_C: 125°C; SizeZ_mm: 0.6; SizeX_mm: 1; SizeY_mm: 0.5; Cap_F: 100nF; AEC Category: Q200
R95-R106 = CMP-0026880-3: as R65 on sheet TIDA-010948-CB-Debug
R241 R268 R276 R281 R291 R317 = CMP-0026992-3: as R61 on sheet TIDA-010948-CB-Debug
U18-U20 = CMP-0079319-1: Quad-Bit Bus Transceiver with Configurable Voltage Translation and 3-State Outputs, PW0016A (TSSOP-16); Alternate PartNumber: SN74AXC4T245PWR; Alternate Manufacturer: Texas Instruments; SizeAreaWB_mm2: 58.8; SizeZ_mm: 1.2; SizeX_mm: 6.4; SizeY_mm: 5; SizeArea_mm2: 32; CompType: IC; AEC Qualified: N; AEC Category: Q200

## Sheet TIDA-010948-CB-PRUIO_CLKGEN.SchDoc
size 431 x 279 mm; Date: Not shown in title block; ApprovedBy: Not shown in title block; CheckedBy: Not shown in title block; Author: Not shown in title block; CompanyName: Not shown in title block; Engineer: Not shown in title block; Organization: Not shown in title block; Address1: Not shown in title block; Address2: Not shown in title block; Address3: Not shown in title block; Address4: Not shown in title block; DocumentNumber: 6; Revision: Use project parameter SCH_Rev; SheetNumber: 6; SheetTotal: 11; PageSetup: Record=PageOptions¦CenterHorizontal=True¦CenterVertical=True¦PrintScale=1.00¦XCorrection=1.00¦YCorrection=1.00¦PrintKind=0¦BorderSize=5000000¦LeftOffset=0¦BottomOffset=0¦Orientation=2¦PaperLength=1000¦PaperWidth=1000¦Scale=100¦PaperSource=15¦PrintQuality=600¦MediaType=1¦DitherType=10¦PaperKind=Letter¦PrintScaleMode=1
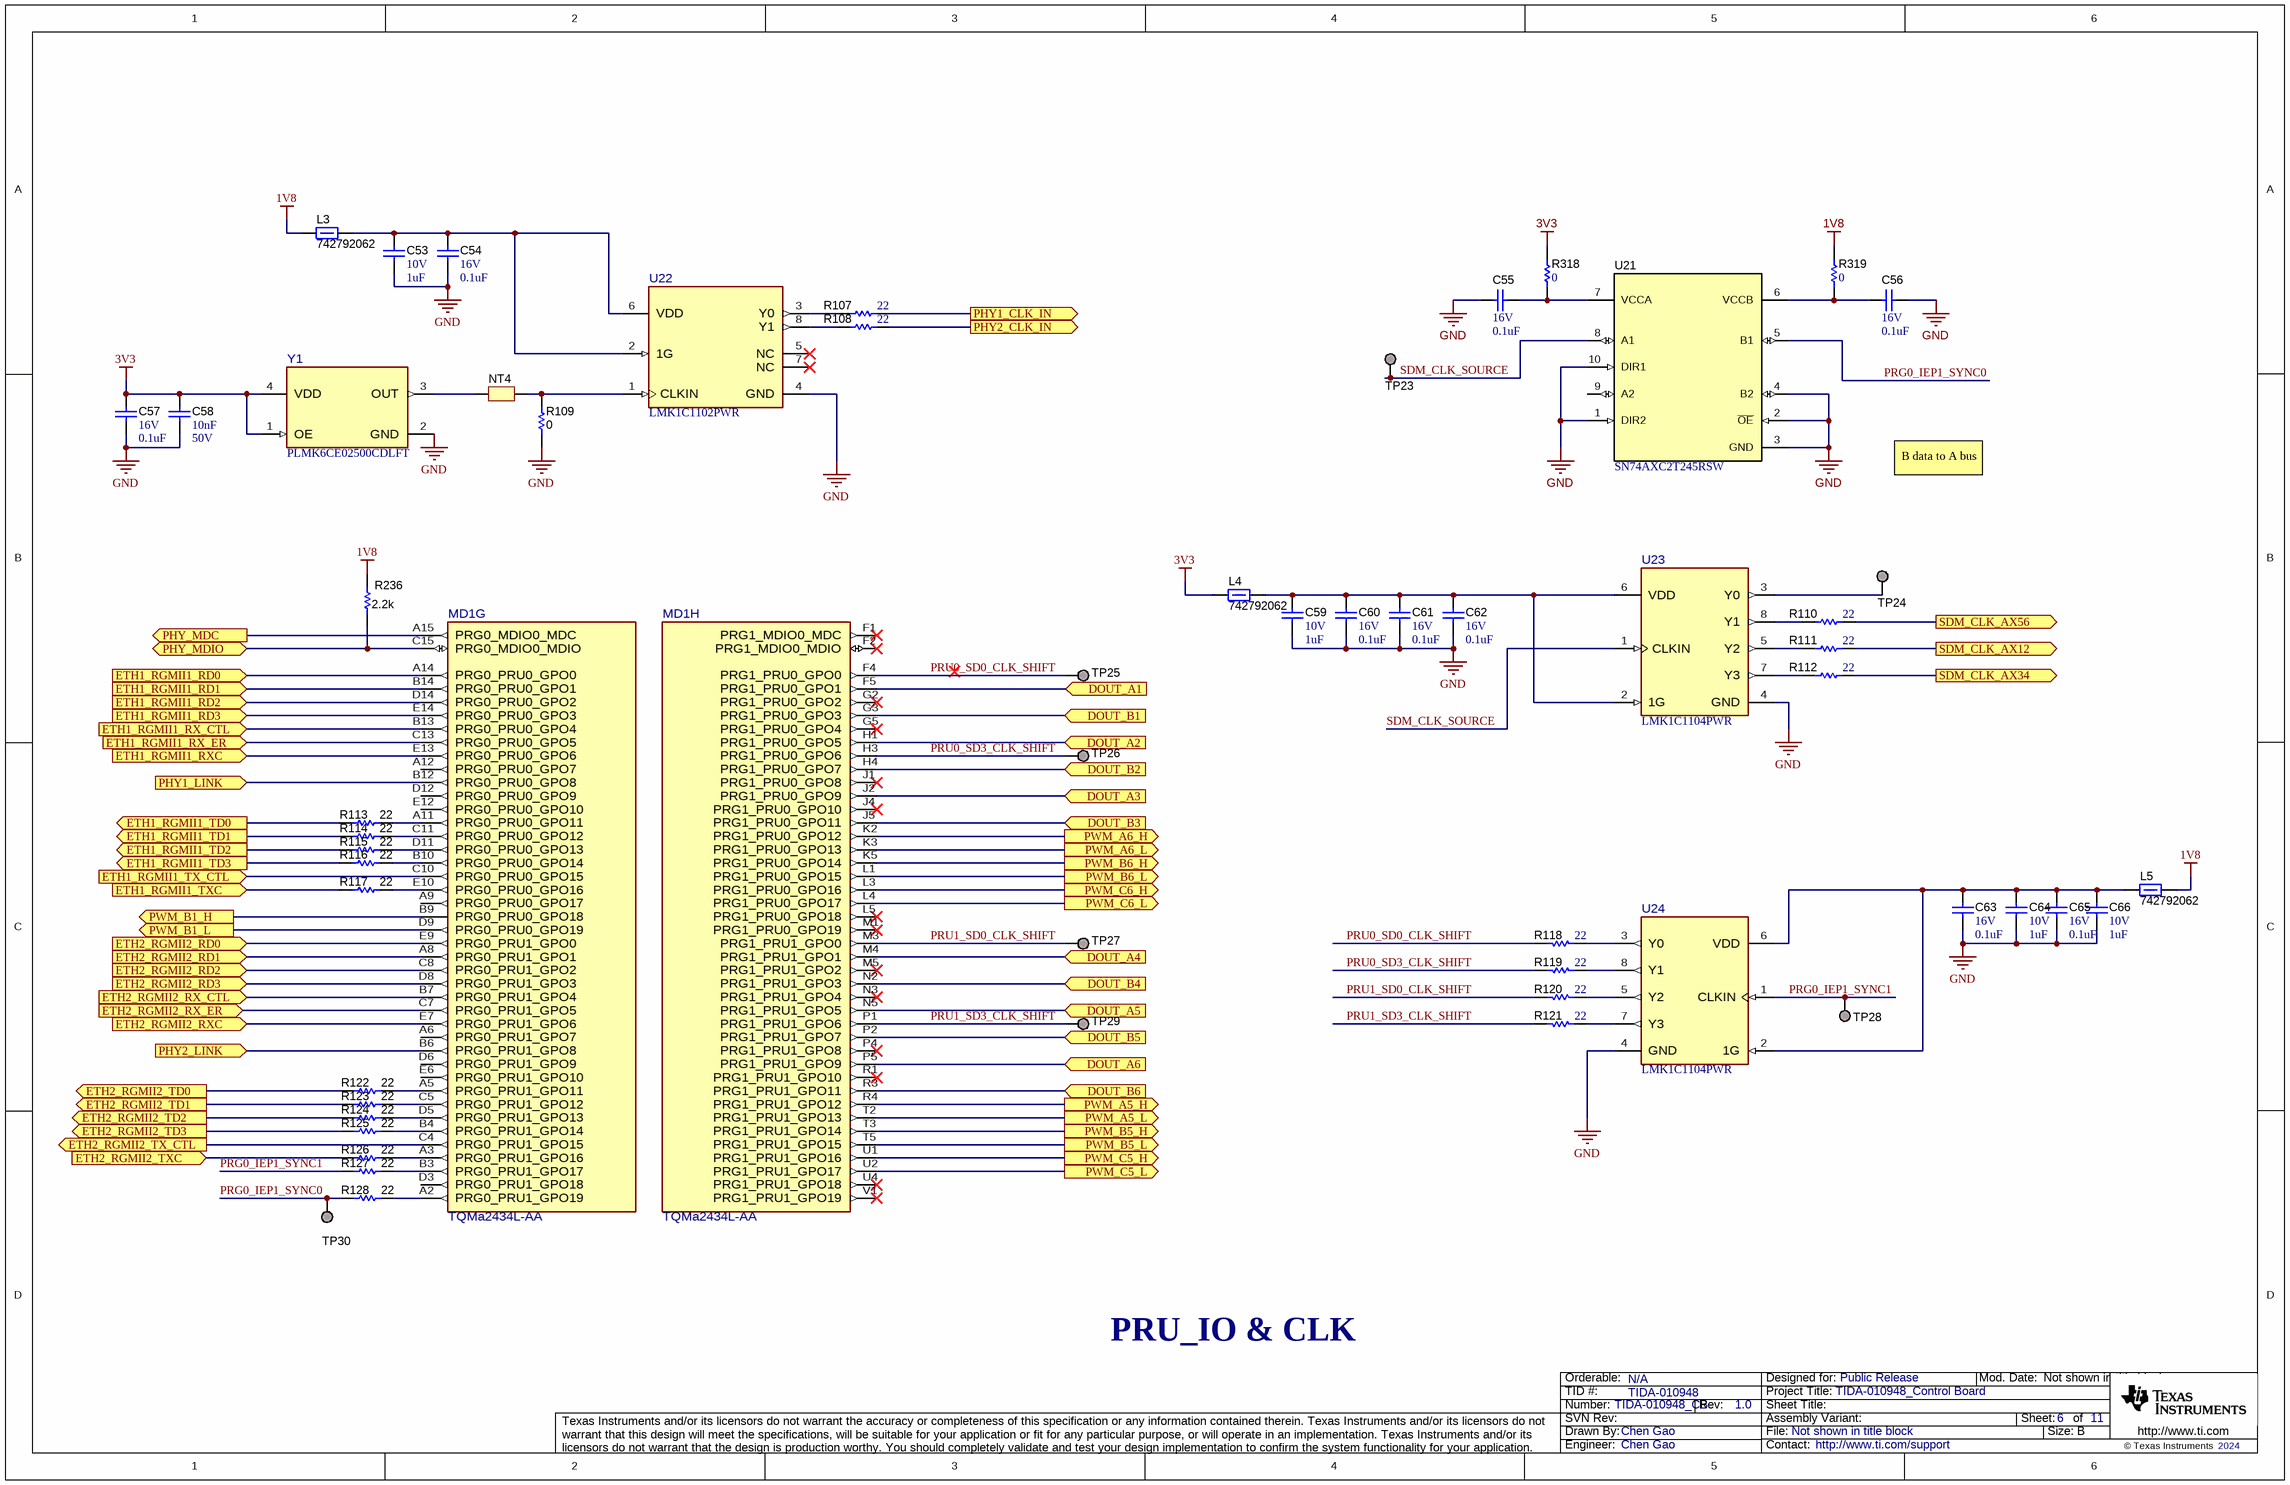
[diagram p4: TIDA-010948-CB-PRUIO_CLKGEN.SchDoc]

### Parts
C53  VDC_V: 10V  ValueDisplayed: 1uF  [0402L]  (hidden comment: 885012105012)
C54  VDC_V: 16V  ValueDisplayed: 0.1uF  [0402L]  (hidden comment: 885012105016)
C55  VDC_V: 16V  ValueDisplayed: 0.1uF  [0201]  (hidden comment: GRM033Z71C104KE14D)
C56  VDC_V: 16V  ValueDisplayed: 0.1uF  [0201]  (hidden comment: GRM033Z71C104KE14D)
C57  VDC_V: 16V  ValueDisplayed: 0.1uF  [0402L]  (hidden comment: 885012105016)
C58  Cap_F: 10nF  VDC_V: 50V  [0805L]  (hidden comment: 885012207092)
C59  VDC_V: 10V  ValueDisplayed: 1uF  [0402L]  (hidden comment: 885012105012)
C60  VDC_V: 16V  ValueDisplayed: 0.1uF  [0402L]  (hidden comment: 885012105016)
C61  VDC_V: 16V  ValueDisplayed: 0.1uF  [0402L]  (hidden comment: 885012105016)
C62  VDC_V: 16V  ValueDisplayed: 0.1uF  [0402L]  (hidden comment: 885012105016)
C63  VDC_V: 16V  ValueDisplayed: 0.1uF  [0402L]  (hidden comment: 885012105016)
C64  VDC_V: 10V  ValueDisplayed: 1uF  [0402L]  (hidden comment: 885012105012)
C65  VDC_V: 16V  ValueDisplayed: 0.1uF  [0402L]  (hidden comment: 885012105016)
C66  VDC_V: 10V  ValueDisplayed: 1uF  [0402L]  (hidden comment: 885012105012)
L3  742792062  [0805_HV]
L4  742792062  [0805_HV]
L5  742792062  [0805_HV]
MD1  TQMa2434L-AA  [FP-TQMa2434L-AA_LGA366-MFG]  (parts G,H of 9)
NT4  Net-Tie  [NetTie_0402]  (value not drawn)  (net tie, no BOM)
R107  ValueDisplayed: 22  [0402L]  (hidden comment: CRCW040222R0JNED)
R108  ValueDisplayed: 22  [0402L]  (hidden comment: CRCW040222R0JNED)
R109  ValueDisplayed: 0  [0402L]  (hidden comment: RC0402JR-070RL)
R110  ValueDisplayed: 22  [0402L]  (hidden comment: CRCW040222R0JNED)
R111  ValueDisplayed: 22  [0402L]  (hidden comment: CRCW040222R0JNED)
R112  ValueDisplayed: 22  [0402L]  (hidden comment: CRCW040222R0JNED)
R113  ValueDisplayed: 22  [0402]  (hidden comment: CRCW040222R0JNED)
R114  ValueDisplayed: 22  [0402]  (hidden comment: CRCW040222R0JNED)
R115  ValueDisplayed: 22  [0402]  (hidden comment: CRCW040222R0JNED)
R116  ValueDisplayed: 22  [0402]  (hidden comment: CRCW040222R0JNED)
R117  ValueDisplayed: 22  [0402]  (hidden comment: CRCW040222R0JNED)
R118  ValueDisplayed: 22  [0402L]  (hidden comment: CRCW040222R0JNED)
R119  ValueDisplayed: 22  [0402L]  (hidden comment: CRCW040222R0JNED)
R120  ValueDisplayed: 22  [0402L]  (hidden comment: CRCW040222R0JNED)
R121  ValueDisplayed: 22  [0402L]  (hidden comment: CRCW040222R0JNED)
R122  ValueDisplayed: 22  [0402]  (hidden comment: CRCW040222R0JNED)
R123  ValueDisplayed: 22  [0402]  (hidden comment: CRCW040222R0JNED)
R124  ValueDisplayed: 22  [0402]  (hidden comment: CRCW040222R0JNED)
R125  ValueDisplayed: 22  [0402]  (hidden comment: CRCW040222R0JNED)
R126  ValueDisplayed: 22  [0402]  (hidden comment: CRCW040222R0JNED)
R127  ValueDisplayed: 22  [0402]  (hidden comment: CRCW040222R0JNED)
R128  ValueDisplayed: 22  [0402]  (hidden comment: CRCW040222R0JNED)
R236  ValueDisplayed: 2.2k  [0402]  (hidden comment: CRCW04022K20JNED)
R318  ValueDisplayed: 0  [0402L]  (hidden comment: ERJ-2GE0R00X)
R319  ValueDisplayed: 0  [0402L]  (hidden comment: ERJ-2GE0R00X)
TP23  TESTPOINT  [TP_25MIL-SMT]  (value not drawn)  (no BOM)
TP24  TESTPOINT  [TP_25MIL-SMT]  (value not drawn)  (no BOM)
TP25  TESTPOINT  [TP_25MIL-SMT]  (value not drawn)  (no BOM)
TP26  TESTPOINT  [TP_25MIL-SMT]  (value not drawn)  (no BOM)
TP27  TESTPOINT  [TP_25MIL-SMT]  (value not drawn)  (no BOM)
TP28  TESTPOINT  [TP_25MIL-SMT]  (value not drawn)  (no BOM)
TP29  TESTPOINT  [TP_25MIL-SMT]  (value not drawn)  (no BOM)
TP30  TESTPOINT  [TP_25MIL-SMT]  (value not drawn)  (no BOM)
U21  SN74AXC2T245RSW  [RSW0010A]
U22  LMK1C1102PWR  [PW0008A-MFG]
U23  LMK1C1104PWR  [PW0008A-MFG]
U24  LMK1C1104PWR  [PW0008A-MFG]
Y1  PLMK6CE02500CDLFT  [DLF0004A-MFG]

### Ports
DOUT_A1 (in), DOUT_A2 (in), DOUT_A3 (in), DOUT_A4 (in), DOUT_A5 (in), DOUT_A6 (in), DOUT_B1 (in), DOUT_B2 (in), DOUT_B3 (in), DOUT_B4 (in), DOUT_B5 (in), DOUT_B6 (in), ETH1_RGMII1_RD0 (in), ETH1_RGMII1_RD1 (in), ETH1_RGMII1_RD2 (in), ETH1_RGMII1_RD3 (in), ETH1_RGMII1_RX_CTL (in), ETH1_RGMII1_RX_ER (in), ETH1_RGMII1_RXC (in), ETH1_RGMII1_TD0 (out), ETH1_RGMII1_TD1 (out), ETH1_RGMII1_TD2 (out), ETH1_RGMII1_TD3 (out), ETH1_RGMII1_TX_CTL (in), ETH1_RGMII1_TXC (in), ETH2_RGMII2_RD0 (in), ETH2_RGMII2_RD1 (in), ETH2_RGMII2_RD2 (in), ETH2_RGMII2_RD3 (in), ETH2_RGMII2_RX_CTL (in), ETH2_RGMII2_RX_ER (in), ETH2_RGMII2_RXC (in), ETH2_RGMII2_TD0 (out), ETH2_RGMII2_TD1 (out), ETH2_RGMII2_TD2 (out), ETH2_RGMII2_TD3 (out), ETH2_RGMII2_TX_CTL (out), ETH2_RGMII2_TXC (in), PHY1_CLK_IN (out), PHY1_LINK (in), PHY2_CLK_IN (out), PHY2_LINK (in), PHY_MDC (out), PHY_MDIO (bidir), PWM_A5_H (out), PWM_A5_L (out), PWM_A6_H (out), PWM_A6_L (out), PWM_B1_H (out), PWM_B1_L (out), PWM_B5_H (out), PWM_B5_L (out), PWM_B6_H (out), PWM_B6_L (out), PWM_C5_H (out), PWM_C5_L (out), PWM_C6_H (out), PWM_C6_L (out), SDM_CLK_AX12 (out), SDM_CLK_AX34 (out), SDM_CLK_AX56 (out)

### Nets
1V8: L3.2 L5.2 R236.2 R319.2
3V3: C57.1 C58.1 L4.2 R318.2 Y1.1(OE) Y1.4(VDD)
GND: C53.2 C54.2 C55.2 C56.1 C57.2 C58.2 C59.2 C60.2 C61.2 C62.2 C63.2 C64.2 C65.2 C66.2 R109.2 U21.1(DIR2) U21.2(~{OE}) U21.3(GND) U21.4(B2) U21.10(DIR1) U22.4(GND) U23.4(GND) U24.4(GND) Y1.2(GND)
DOUT_A1: MD1.F5(PRG1_PRU0_GPO1) ; port DOUT_A1
DOUT_A2: MD1.H1(PRG1_PRU0_GPO5) ; port DOUT_A2
DOUT_A3: MD1.J2(PRG1_PRU0_GPO9) ; port DOUT_A3
DOUT_A4: MD1.M4(PRG1_PRU1_GPO1) ; port DOUT_A4
DOUT_A5: MD1.N5(PRG1_PRU1_GPO5) ; port DOUT_A5
DOUT_A6: MD1.P5(PRG1_PRU1_GPO9) ; port DOUT_A6
DOUT_B1: MD1.G3(PRG1_PRU0_GPO3) ; port DOUT_B1
DOUT_B2: MD1.H4(PRG1_PRU0_GPO7) ; port DOUT_B2
DOUT_B3: MD1.J5(PRG1_PRU0_GPO11) ; port DOUT_B3
DOUT_B4: MD1.N2(PRG1_PRU1_GPO3) ; port DOUT_B4
DOUT_B5: MD1.P2(PRG1_PRU1_GPO7) ; port DOUT_B5
DOUT_B6: MD1.R3(PRG1_PRU1_GPO11) ; port DOUT_B6
ETH1_LED_0: MD1.B12(PRG0_PRU0_GPO8) ; port PHY1_LINK
ETH1_RGMII1_RD0: MD1.A14(PRG0_PRU0_GPO0) ; port ETH1_RGMII1_RD0
ETH1_RGMII1_RD1: MD1.B14(PRG0_PRU0_GPO1) ; port ETH1_RGMII1_RD1
ETH1_RGMII1_RD2: MD1.D14(PRG0_PRU0_GPO2) ; port ETH1_RGMII1_RD2
ETH1_RGMII1_RD3: MD1.E14(PRG0_PRU0_GPO3) ; port ETH1_RGMII1_RD3
ETH1_RGMII1_RX_CTL: MD1.B13(PRG0_PRU0_GPO4) ; port ETH1_RGMII1_RX_CTL
ETH1_RGMII1_RX_ER: MD1.C13(PRG0_PRU0_GPO5) ; port ETH1_RGMII1_RX_ER
ETH1_RGMII1_RXC: MD1.E13(PRG0_PRU0_GPO6) ; port ETH1_RGMII1_RXC
ETH1_RGMII1_TD0: R113.1 ; port ETH1_RGMII1_TD0
ETH1_RGMII1_TD1: R114.1 ; port ETH1_RGMII1_TD1
ETH1_RGMII1_TD2: R115.1 ; port ETH1_RGMII1_TD2
ETH1_RGMII1_TD3: R116.1 ; port ETH1_RGMII1_TD3
ETH1_RGMII1_TX_CTL: MD1.C10(PRG0_PRU0_GPO15) ; port ETH1_RGMII1_TX_CTL
ETH1_RGMII1_TXC: R117.1 ; port ETH1_RGMII1_TXC
ETH2_LED_0: MD1.B6(PRG0_PRU1_GPO8) ; port PHY2_LINK
ETH2_RGMII2_RD0: MD1.E9(PRG0_PRU1_GPO0) ; port ETH2_RGMII2_RD0
ETH2_RGMII2_RD1: MD1.A8(PRG0_PRU1_GPO1) ; port ETH2_RGMII2_RD1
ETH2_RGMII2_RD2: MD1.C8(PRG0_PRU1_GPO2) ; port ETH2_RGMII2_RD2
ETH2_RGMII2_RD3: MD1.D8(PRG0_PRU1_GPO3) ; port ETH2_RGMII2_RD3
ETH2_RGMII2_RX_CTL: MD1.B7(PRG0_PRU1_GPO4) ; port ETH2_RGMII2_RX_CTL
ETH2_RGMII2_RX_ER: MD1.C7(PRG0_PRU1_GPO5) ; port ETH2_RGMII2_RX_ER
ETH2_RGMII2_RXC: MD1.E7(PRG0_PRU1_GPO6) ; port ETH2_RGMII2_RXC
ETH2_RGMII2_TD0: R122.1 ; port ETH2_RGMII2_TD0
ETH2_RGMII2_TD1: R123.1 ; port ETH2_RGMII2_TD1
ETH2_RGMII2_TD2: R124.1 ; port ETH2_RGMII2_TD2
ETH2_RGMII2_TD3: R125.1 ; port ETH2_RGMII2_TD3
ETH2_RGMII2_TX_CTL: MD1.C4(PRG0_PRU1_GPO15) ; port ETH2_RGMII2_TX_CTL
ETH2_RGMII2_TXC: R126.1 ; port ETH2_RGMII2_TXC
PHY1_CLK_IN: R107.2 ; port PHY1_CLK_IN
PHY2_CLK_IN: R108.2 ; port PHY2_CLK_IN
PHY_MDC: MD1.A15(PRG0_MDIO0_MDC) ; port PHY_MDC
PHY_MDIO: MD1.C15(PRG0_MDIO0_MDIO) R236.1 ; port PHY_MDIO
PRG0_IEP1_SYNC0: R128.1 TP30.1 U21.5(B1)
PRG0_IEP1_SYNC1: R127.1 TP28.1 U24.1(CLKIN)
PRU0_SD0_CLK_SHIFT: MD1.F4(PRG1_PRU0_GPO0) R118.2 TP25.1
PRU0_SD3_CLK_SHIFT: MD1.H3(PRG1_PRU0_GPO6) R119.2 TP26.1
PRU1_SD0_CLK_SHIFT: MD1.M3(PRG1_PRU1_GPO0) R120.2 TP27.1
PRU1_SD3_CLK_SHIFT: MD1.P1(PRG1_PRU1_GPO6) R121.2 TP29.1
PWM_A5_H: MD1.R4(PRG1_PRU1_GPO12) ; port PWM_A5_H
PWM_A5_L: MD1.T2(PRG1_PRU1_GPO13) ; port PWM_A5_L
PWM_A6_H: MD1.K2(PRG1_PRU0_GPO12) ; port PWM_A6_H
PWM_A6_L: MD1.K3(PRG1_PRU0_GPO13) ; port PWM_A6_L
PWM_B1_H: MD1.B9(PRG0_PRU0_GPO18) ; port PWM_B1_H
PWM_B1_L: MD1.D9(PRG0_PRU0_GPO19) ; port PWM_B1_L
PWM_B5_H: MD1.T3(PRG1_PRU1_GPO14) ; port PWM_B5_H
PWM_B5_L: MD1.T5(PRG1_PRU1_GPO15) ; port PWM_B5_L
PWM_B6_H: MD1.K5(PRG1_PRU0_GPO14) ; port PWM_B6_H
PWM_B6_L: MD1.L1(PRG1_PRU0_GPO15) ; port PWM_B6_L
PWM_C5_H: MD1.U1(PRG1_PRU1_GPO16) ; port PWM_C5_H
PWM_C5_L: MD1.U2(PRG1_PRU1_GPO17) ; port PWM_C5_L
PWM_C6_H: MD1.L3(PRG1_PRU0_GPO16) ; port PWM_C6_H
PWM_C6_L: MD1.L4(PRG1_PRU0_GPO17) ; port PWM_C6_L
SDM_CLK_AX12: R111.2 ; port SDM_CLK_AX12
SDM_CLK_AX34: R112.2 ; port SDM_CLK_AX34
SDM_CLK_AX56: R110.2 ; port SDM_CLK_AX56
SDM_CLK_SOURCE: TP23.1 U21.8(A1) U23.1(CLKIN)
NetC53_1: C53.1 C54.1 L3.1 U22.2(1G) U22.6(VDD)
NetC55_1: C55.1 R318.1 U21.7(VCCA)
NetC56_2: C56.2 R319.1 U21.6(VCCB)
NetC59_1: C59.1 C60.1 C61.1 C62.1 L4.1 U23.2(1G) U23.6(VDD)
NetC63_1: C63.1 C64.1 C65.1 C66.1 L5.1 U24.2(1G) U24.6(VDD)
NetMD1_A2: MD1.A2(PRG0_PRU1_GPO19) R128.2
NetMD1_A3: MD1.A3(PRG0_PRU1_GPO16) R126.2
NetMD1_A5: MD1.A5(PRG0_PRU1_GPO11) R122.2
NetMD1_A11: MD1.A11(PRG0_PRU0_GPO11) R113.2
NetMD1_B3: MD1.B3(PRG0_PRU1_GPO17) R127.2
NetMD1_B4: MD1.B4(PRG0_PRU1_GPO14) R125.2
NetMD1_B10: MD1.B10(PRG0_PRU0_GPO14) R116.2
NetMD1_C5: MD1.C5(PRG0_PRU1_GPO12) R123.2
NetMD1_C11: MD1.C11(PRG0_PRU0_GPO12) R114.2
NetMD1_D5: MD1.D5(PRG0_PRU1_GPO13) R124.2
NetMD1_D11: MD1.D11(PRG0_PRU0_GPO13) R115.2
NetMD1_E10: MD1.E10(PRG0_PRU0_GPO16) R117.2
NetNT4_1: NT4.1 Y1.3(OUT)
NetNT4_2: NT4.2 R109.1 U22.1(CLKIN)
NetR107_1: R107.1 U22.3(Y0)
NetR108_1: R108.1 U22.8(Y1)
NetR110_1: R110.1 U23.8(Y1)
NetR111_1: R111.1 U23.5(Y2)
NetR112_1: R112.1 U23.7(Y3)
NetR118_1: R118.1 U24.3(Y0)
NetR119_1: R119.1 U24.8(Y1)
NetR120_1: R120.1 U24.5(Y2)
NetR121_1: R121.1 U24.7(Y3)
NetTP24_1: TP24.1 U23.3(Y0)

Not connected (* = marked no-connect by the designer): MD1 A6(PRG0_PRU1_GPO7) A9(PRG0_PRU0_GPO17) A12(PRG0_PRU0_GPO7) D3(PRG0_PRU1_GPO18) D6(PRG0_PRU1_GPO9) D12(PRG0_PRU0_GPO9) E6(PRG0_PRU1_GPO10) E12(PRG0_PRU0_GPO10) F1(PRG1_MDIO0_MDC)* F2(PRG1_MDIO0_MDIO)* G2(PRG1_PRU0_GPO2)* G5(PRG1_PRU0_GPO4)* J1(PRG1_PRU0_GPO8)* J4(PRG1_PRU0_GPO10)* L5(PRG1_PRU0_GPO18)* M1(PRG1_PRU0_GPO19)* M5(PRG1_PRU1_GPO2)* N3(PRG1_PRU1_GPO4)* P4(PRG1_PRU1_GPO8)* R1(PRG1_PRU1_GPO10)* U4(PRG1_PRU1_GPO18)* V1(PRG1_PRU1_GPO19)*; U21 9(A2); U22 5(NC)* 7(NC)*

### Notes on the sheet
- B data to A bus
- PRU_IO & CLK

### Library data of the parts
C53 C59 C64 C66 = CMP-0064924-2: as C44 on sheet TIDA-010948-CB-Debug
C54 C57 C60-C63 C65 = CMP-0006223-2: as C34-C37 on sheet TIDA-010948-CB-Debug
C55 C56 = CMP-0064970-1: CAP, CERM, 0.1 uF, 16 V,+/- 10%, X7R, 0201; Manufacturer: MuRata; TaMin_C: -55°C; Polarized: N; SizeAreaWB_mm2: 2.08; Value1: Unknown; U/M: EA; Value: 0.1uF; TaMax_C: 125°C; SizeZ_mm: 0.26; SizeX_mm: 0.6; SizeY_mm: 0.3; SizeArea_mm2: 0.18; Cap_F: 100nF; AEC Category: Q200
C58 = CMP-0007694-2: CAP, CERM, 0.01 uF, 50 V, +/- 10%, X7R, 0805; Manufacturer: Wurth Elektronik; TaMin_C: -55°C; Polarized: N; SizeAreaWB_mm2: 6.75; Value1: Unknown; U/M: EA; Value: 0.01uF; TaMax_C: 125°C; SizeZ_mm: 1.45; SizeX_mm: 2; SizeY_mm: 1.25; Cap_Case: 0805; SizeArea_mm2: 2.5; AEC Category: Q200
L3-L5 = CMP-0003092-1: Ferrite Bead, 80 ohm @ 100 MHz, 0.5 A, 0805; Manufacturer: Wurth Elektronik; Ztyp@1GHz_Ohm: 146.576; ZTyp@100MHz_Ohm: 80; SizeAreaWB_mm2: 6.75; DCR_ohm: 0.2; Value1: 0.2 ohm; Value: 80 ohm; Imax_A: 500mA; SizeZ_mm: 1.45; SizeX_mm: 2; SizeY_mm: 1.25; Value2: 0.5A; SizeArea_mm2: 2.5
MD1 = CMP-0120622-1: as MD1 on sheet TIDA-010948-CB-Debug
NT4 = CMP-0078142-5: Single point connection between nets.
R107 R108 R110-R128 = CMP-0026880-3: as R65 on sheet TIDA-010948-CB-Debug
R109 = CMP-0027004-2: RES, 0, 5%, 0.063 W, 0402; Manufacturer: Yageo America; Power_W: 63mW; TempCo: 200 ppm/C; Value_Code: 0000; U/M: EA; Value: 0; EIA_Code: E24; SizeX_mm: 1; SizeY_mm: 0.5; SizeZ_mm: 0.6; Value2: 0.063W; VDC_V: 50V; AEC Category: Q200
R236 = CMP-0026890-5: RES, 2.2 k, 5%, 0.063 W, AEC-Q200 Grade 0, 0402; Manufacturer: Vishay-Dale; Power_W: 63mW; TempCo: 200 ppm/C; Value_Code: 2k20; Value: 2.2k; EIA_Code: E24; SizeX_mm: 1; SizeY_mm: 0.5; SizeZ_mm: 0.6; Value2: 0.063W; AEC Qualified: Y; VDC_V: 50V; AEC Category: Q200; AEC Grade: 0
R318 R319 = CMP-0026992-3: as R61 on sheet TIDA-010948-CB-Debug
TP23-TP30 = CMP-0078143-3: TEST POINT.  No entry in BOM.
U21 = CMP-0860382-1: SN74AXC2T245RSW, RSW0010A (UQFN-10); Alternate Manufacturer: Texas Instruments; SizeZ_mm: 0.55; AEC Qualified: N; SizeArea_mm2: 2.52; CompType: IC; SizeX_mm: 1.4; SizeY_mm: 1.8; AEC Category: Q200; SizeAreaWB_mm2: 6.72
U22 = CMP-0091149-1: Clock Clock Buffer IC 1:4 250MHz 8-TSSOP (0.173", 4.40mm Width); Manufacturer: Texas Instruments; Standoff Height: 0.05mm; SizeZ_mm: 1.2mm; Propagation Delay: 1.5ns; AEC Qualified: No; Number Of Outputs: 2; Nominal Supply Current: 25-33000uA; TaMin_C: -40°C; Min Supply Voltage: 1.71V; Max Supply Voltage: 3.465V; Number Of Elements: 1; TJmax_C: +150°C; TaMax_C: +125°C
U23 U24 = CMP-0096980-1: 1.8-V, 2.5-V, and 3.3-V LVCMOS Clock Buffer Family; Manufacturer: Texas Instruments; Logic Function: Non-Inverting; TaMax_C: +125°C; TJmax_C: +150°C; Max Supply Voltage: 3.465V; Number Of Elements: 5; TaMin_C: -40°C; Nominal Supply Current: 25-33000uA; Number Of Outputs: 4; Number Of Inputs: 1; AEC Qualified: No; Min Supply Voltage: 1.71V; SizeZ_mm: 1.2mm; Standoff Height: 0.05mm; Propagation Delay: 1.5ns
Y1 = CMP-0096024-1: High-Performance BAW Oscillator; Manufacturer: Texas Instruments; Load Capacitance: 30pF; TJmax_C: +125°C; Frequency Stability: 25ppm; SizeZ_mm: 1mm; Max Supply Current: 50mA; Min Supply Voltage: 2.375V; Standoff Height: 0mm; Frequency_Fixed: 25MHz; Max Supply Voltage: 3.465V; TaMax_C: +105°C; AEC Qualified: No; TaMin_C: -40°C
